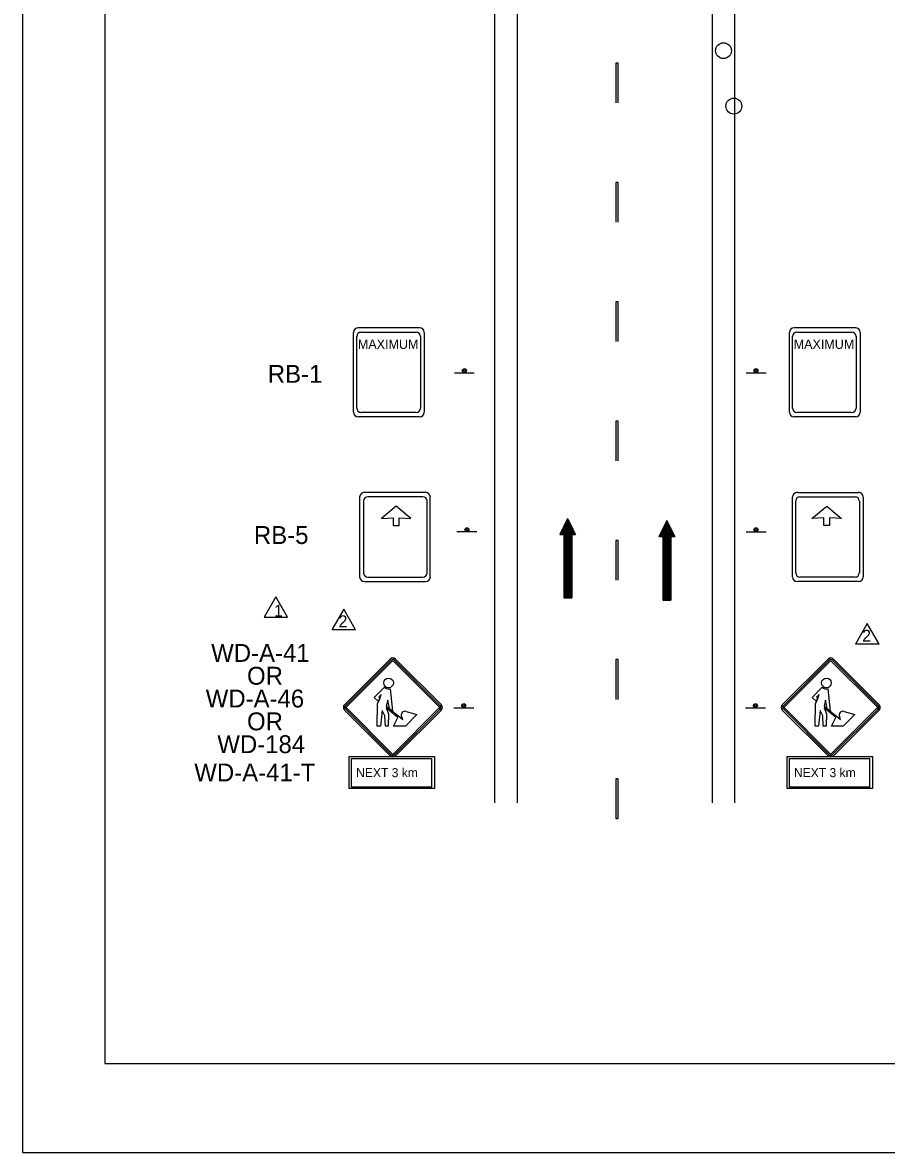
# Model space of a CAD drawing. Extents: x 1333 to 1549, y 120 to 399.
# Drawn here: x 1333.4 to 1438.4, y 119.8 to 257.2 of the extents above; entities that cross this region are included whole.
import ezdxf

# ---------------------------------------------------------------- set-up
doc = ezdxf.new("R2010")
doc.units = 0
for name, color, linetype in [('Level 1', 7, 'Continuous'), ('Level 10', 7, 'Continuous'), ('Level 2', 7, 'Continuous'), ('Level 44', 7, 'Continuous'), ('Level 5', 7, 'Continuous'), ('Level 60', 7, 'Continuous'), ('Level 63', 7, 'Continuous')]:
    doc.layers.add(name, color=color, linetype=linetype)

msp = doc.modelspace()

# ---------------------------------------------------------------- linework, layer by layer
at = {"layer": 'Level 1'}
for p, q in [((1378.07, 179.78), (1372.49, 174.21)), ((1378.19, 179.66), (1372.62, 174.09)), ((1378.32, 179.53), (1372.74, 173.96)), ((1384.03, 173.96), (1378.45, 179.53)), ((1384.15, 174.08), (1378.58, 179.66)), ((1384.28, 174.21), (1378.7, 179.78)), ((1431.32, 179.78), (1425.74, 174.21)), ((1431.44, 179.66), (1425.87, 174.09)), ((1431.57, 179.53), (1425.99, 173.96)), ((1437.28, 173.96), (1431.7, 179.53)), ((1437.4, 174.08), (1431.83, 179.66)), ((1437.52, 174.21), (1431.95, 179.78)), ((1378.13, 177.34), (1378.11, 177.34)), ((1431.37, 177.34), (1431.36, 177.34)), ((1372.49, 173.58), (1378.07, 168.01)), ((1372.62, 173.71), (1378.19, 168.13)), ((1372.74, 173.83), (1378.32, 168.25)), ((1378.45, 168.25), (1384.03, 173.83)), ((1378.57, 168.13), (1384.15, 173.7)), ((1378.7, 168.01), (1384.28, 173.58)), ((1425.74, 173.58), (1431.32, 168.01)), ((1425.87, 173.71), (1431.44, 168.13)), ((1425.99, 173.83), (1431.56, 168.25)), ((1431.7, 168.25), (1437.28, 173.83)), ((1431.82, 168.13), (1437.4, 173.7)), ((1431.95, 168.01), (1437.52, 173.58))]:
    msp.add_line(p, q, dxfattribs=at)
for points in [[(1364.16, 187.35), (1362.75, 184.88), (1365.58, 184.88)], [(1376.66, 175.13), (1376.8, 175.02), (1376.97, 175.45)], [(1377.97, 173.75), (1377.76, 174.77), (1377.59, 174.06)], [(1429.91, 175.13), (1430.05, 175.02), (1430.22, 175.45)], [(1431.21, 173.75), (1431.01, 174.77), (1430.84, 174.06)]]:
    msp.add_lwpolyline(points, close=True, dxfattribs=at)
for points in [[(1376.66, 175.13), (1376.8, 175.02), (1376.64, 174.62), (1376.13, 175.1), (1377.35, 176.35)], [(1376.66, 175.13), (1376.8, 175.02), (1376.64, 174.62), (1376.13, 175.1), (1377.35, 176.35)], [(1377.08, 173.52), (1376.9, 171.62), (1376.48, 171.62), (1376.53, 174.35), (1376.64, 174.62), (1376.13, 175.1), (1377.35, 176.35)], [(1378.05, 176.17), (1378.33, 173.45), (1377.97, 173.75), (1377.76, 174.77), (1377.59, 174.06), (1379.58, 172.42), (1379.44, 172.78)], [(1378.05, 176.17), (1378.33, 173.45), (1377.97, 173.75), (1377.76, 174.77), (1377.59, 174.06), (1379.58, 172.42), (1379.44, 172.78)], [(1378.05, 176.17), (1378.33, 173.45), (1379.58, 172.42), (1379.44, 172.78)], [(1429.91, 175.13), (1430.05, 175.02), (1429.89, 174.62), (1429.38, 175.1), (1430.6, 176.35)], [(1429.91, 175.13), (1430.05, 175.02), (1429.89, 174.62), (1429.38, 175.1), (1430.6, 176.35)], [(1430.33, 173.52), (1430.15, 171.62), (1429.72, 171.62), (1429.78, 174.35), (1429.89, 174.62), (1429.38, 175.1), (1430.6, 176.35)], [(1431.29, 176.17), (1431.58, 173.45), (1431.21, 173.75), (1431.01, 174.77), (1430.84, 174.06), (1432.83, 172.42), (1432.69, 172.78)], [(1431.29, 176.17), (1431.58, 173.45), (1431.21, 173.75), (1431.01, 174.77), (1430.84, 174.06), (1432.83, 172.42), (1432.69, 172.78)], [(1431.29, 176.17), (1431.58, 173.45), (1432.83, 172.42), (1432.69, 172.78)], [(1380.02, 173.4), (1381.3, 173.02), (1379.91, 171.62), (1378.46, 171.62), (1379, 172.68), (1377.59, 173.83), (1377.87, 173.1), (1377.83, 171.62), (1377.48, 171.62), (1377.42, 172.88), (1377.08, 173.52), (1376.9, 171.62), (1376.48, 171.62), (1376.53, 174.35), (1376.97, 175.45), (1376.66, 175.13)], [(1380.02, 173.4), (1381.3, 173.02), (1379.91, 171.62), (1378.46, 171.62), (1379, 172.68), (1377.59, 173.83), (1377.87, 173.1), (1377.83, 171.62), (1377.48, 171.62), (1377.42, 172.88), (1377.08, 173.52), (1376.9, 171.62), (1376.48, 171.62), (1376.53, 174.35), (1376.97, 175.45), (1376.66, 175.13)], [(1433.27, 173.4), (1434.55, 173.02), (1433.16, 171.62), (1431.71, 171.62), (1432.25, 172.68), (1430.84, 173.83), (1431.12, 173.1), (1431.08, 171.62), (1430.73, 171.62), (1430.67, 172.88), (1430.33, 173.52), (1430.15, 171.62), (1429.72, 171.62), (1429.78, 174.35), (1430.22, 175.45), (1429.91, 175.13)], [(1433.27, 173.4), (1434.55, 173.02), (1433.16, 171.62), (1431.71, 171.62), (1432.25, 172.68), (1430.84, 173.83), (1431.12, 173.1), (1431.08, 171.62), (1430.73, 171.62), (1430.67, 172.88), (1430.33, 173.52), (1430.15, 171.62), (1429.72, 171.62), (1429.78, 174.35), (1430.22, 175.45), (1429.91, 175.13)], [(1380.02, 173.4), (1381.3, 173.02), (1379.91, 171.62), (1378.46, 171.62), (1379, 172.68), (1377.59, 173.83), (1377.87, 173.1), (1377.83, 171.62), (1377.48, 171.62), (1377.42, 172.88), (1377.08, 173.52)], [(1433.27, 173.4), (1434.55, 173.02), (1433.16, 171.62), (1431.71, 171.62), (1432.25, 172.68), (1430.84, 173.83), (1431.12, 173.1), (1431.08, 171.62), (1430.73, 171.62), (1430.67, 172.88), (1430.33, 173.52)]]:
    msp.add_lwpolyline(points, dxfattribs=at)
for centre in [(1377.86, 176.88), (1377.86, 176.88), (1377.86, 176.88), (1431.11, 176.88), (1431.11, 176.88), (1431.11, 176.88)]:
    msp.add_circle(centre, 0.591, dxfattribs=at)
for centre, radius, start, end in [((1378.39, 179.47), 0.446, 45, 134.9651), ((1378.39, 179.47), 0.27, 45, 134.9651), ((1378.39, 179.47), 0.0948, 45, 134.9651), ((1431.63, 179.47), 0.446, 45, 134.9651), ((1431.63, 179.47), 0.27, 45, 134.9651), ((1431.63, 179.47), 0.0948, 45, 134.9651), ((1377.86, 176.88), 0.734, 226.3135, 284.9576), ((1377.86, 176.88), 0.734, 226.3135, 284.9576), ((1377.86, 176.88), 0.734, 226.3135, 284.9576), ((1431.11, 176.88), 0.734, 226.3135, 284.9576), ((1431.11, 176.88), 0.734, 226.3135, 284.9576), ((1431.11, 176.88), 0.734, 226.3135, 284.9576), ((1372.81, 173.9), 0.446, 134.965, 225), ((1372.81, 173.9), 0.27, 134.965, 225), ((1372.81, 173.9), 0.0948, 134.965, 225), ((1379.88, 172.95), 0.475, 73.381, 201.0999), ((1379.88, 172.95), 0.475, 73.381, 201.0999), ((1379.88, 172.95), 0.475, 73.381, 201.0999), ((1383.96, 173.89), 0.0948, 314.9651, 45), ((1383.96, 173.89), 0.27, 314.9651, 45), ((1383.96, 173.89), 0.446, 314.9651, 45), ((1426.06, 173.9), 0.446, 134.965, 225), ((1426.06, 173.9), 0.27, 134.965, 225), ((1426.06, 173.9), 0.0948, 134.965, 225), ((1433.13, 172.95), 0.475, 73.381, 201.0999), ((1433.13, 172.95), 0.475, 73.381, 201.0999), ((1433.13, 172.95), 0.475, 73.381, 201.0999), ((1437.21, 173.89), 0.0948, 314.9651, 45), ((1437.21, 173.89), 0.27, 314.9651, 45), ((1437.21, 173.89), 0.446, 314.9651, 45), ((1378.38, 168.32), 0.446, 225, 314.9652), ((1378.38, 168.32), 0.27, 225, 314.9652), ((1378.38, 168.32), 0.0948, 225, 314.9652), ((1431.63, 168.32), 0.446, 225, 314.9652), ((1431.63, 168.32), 0.27, 225, 314.9652), ((1431.63, 168.32), 0.0948, 225, 314.9652)]:
    msp.add_arc(centre, radius, start, end, dxfattribs=at)
at = {"layer": 'Level 10'}
for p, q in [((1390.76, 343.79), (1390.76, 162.28)), ((1393.49, 343.79), (1393.49, 162.28)), ((1417.2, 343.79), (1417.2, 162.28)), ((1419.94, 343.79), (1419.94, 162.28)), ((1417.42, 237.37), (1417.43, 237.37)), ((1399.64, 196.89), (1398.68, 194.95)), ((1399.52, 196.64), (1399.52, 187.21)), ((1399.64, 196.89), (1399.64, 187.21)), ((1399.64, 196.89), (1400.61, 194.95)), ((1399.77, 196.64), (1399.77, 187.21)), ((1411.7, 196.62), (1410.74, 194.69)), ((1411.7, 196.62), (1411.7, 186.94)), ((1411.7, 196.62), (1412.67, 194.69)), ((1398.92, 195.44), (1398.92, 194.95)), ((1399.04, 195.68), (1399.04, 194.95)), ((1399.16, 195.92), (1399.16, 187.21)), ((1399.28, 196.16), (1399.28, 187.21)), ((1399.4, 196.4), (1399.4, 187.21)), ((1399.89, 196.4), (1399.89, 187.21)), ((1400.01, 196.16), (1400.01, 187.21)), ((1400.13, 195.92), (1400.13, 187.21)), ((1400.25, 195.68), (1400.25, 194.95)), ((1400.37, 195.44), (1400.37, 194.95)), ((1411.1, 195.41), (1411.1, 194.69)), ((1411.22, 195.65), (1411.22, 186.94)), ((1411.34, 195.9), (1411.34, 186.94)), ((1411.46, 196.14), (1411.46, 186.94)), ((1411.58, 196.38), (1411.58, 186.94)), ((1411.83, 196.38), (1411.83, 186.94)), ((1411.95, 196.14), (1411.95, 186.94)), ((1412.07, 195.9), (1412.07, 186.94)), ((1412.19, 195.65), (1412.19, 186.94)), ((1412.31, 195.41), (1412.31, 194.69)), ((1398.68, 194.95), (1399.16, 194.95)), ((1398.8, 195.19), (1398.8, 194.95)), ((1399.16, 194.95), (1399.16, 187.21)), ((1400.13, 194.95), (1400.13, 187.21)), ((1400.13, 194.95), (1400.61, 194.95)), ((1400.49, 195.19), (1400.49, 194.95)), ((1410.74, 194.69), (1411.22, 194.69)), ((1410.86, 194.93), (1410.86, 194.69)), ((1410.98, 195.17), (1410.98, 194.69)), ((1411.22, 194.69), (1411.22, 186.94)), ((1412.19, 194.69), (1412.19, 186.94)), ((1412.19, 194.69), (1412.67, 194.69)), ((1412.43, 195.17), (1412.43, 194.69)), ((1412.55, 194.93), (1412.55, 194.69)), ((1399.16, 187.21), (1400.13, 187.21)), ((1411.22, 186.94), (1412.19, 186.94)), ((1390.76, 162.28), (1390.76, 162.28))]:
    msp.add_line(p, q, dxfattribs=at)
for centre in [(1418.59, 253.8), (1419.85, 247.06)]:
    msp.add_circle(centre, 0.968, dxfattribs=at)
at = {"layer": 'Level 2'}
for p, q in [((1405.51, 252.28), (1405.51, 247.44)), ((1405.8, 252.28), (1405.51, 252.28)), ((1405.8, 247.44), (1405.8, 252.28)), ((1405.51, 237.77), (1405.51, 232.93)), ((1405.8, 237.77), (1405.51, 237.77)), ((1405.8, 232.93), (1405.8, 237.77)), ((1405.51, 223.25), (1405.51, 218.41)), ((1405.8, 223.25), (1405.51, 223.25)), ((1405.8, 218.41), (1405.8, 223.25)), ((1405.51, 208.74), (1405.51, 203.9)), ((1405.8, 208.74), (1405.51, 208.74)), ((1405.8, 203.9), (1405.8, 208.74)), ((1405.51, 194.22), (1405.51, 189.39)), ((1405.8, 194.22), (1405.51, 194.22)), ((1405.8, 189.39), (1405.8, 194.22)), ((1405.51, 179.71), (1405.51, 174.87)), ((1405.8, 179.71), (1405.51, 179.71)), ((1405.8, 174.87), (1405.8, 179.71)), ((1405.51, 165.2), (1405.51, 160.36)), ((1405.8, 165.2), (1405.51, 165.2)), ((1405.8, 160.36), (1405.8, 165.2)), ((1405.51, 160.36), (1405.8, 160.36))]:
    msp.add_line(p, q, dxfattribs=at)
at = {"layer": 'Level 44'}
for p, q in [((1374.18, 220.1), (1381.63, 220.1)), ((1427.18, 220.1), (1434.63, 220.1)), ((1373.61, 209.82), (1373.61, 219.53)), ((1373.99, 210.31), (1373.99, 219.05)), ((1374.51, 219.56), (1381.21, 219.56)), ((1381.73, 219.05), (1381.73, 210.31)), ((1382.2, 219.53), (1382.2, 209.82)), ((1426.6, 209.82), (1426.6, 219.53)), ((1426.99, 210.31), (1426.99, 219.05)), ((1427.5, 219.56), (1434.21, 219.56)), ((1434.73, 219.05), (1434.73, 210.31)), ((1435.2, 219.53), (1435.2, 209.82)), ((1385.88, 214.59), (1388.29, 214.59)), ((1421.34, 214.59), (1423.76, 214.59)), ((1373.61, 209.81), (1373.61, 209.82)), ((1373.99, 210.31), (1373.99, 210.31)), ((1381.63, 209.24), (1374.18, 209.24)), ((1374.31, 209.48), (1374.31, 209.48)), ((1381.21, 209.79), (1374.51, 209.79)), ((1426.6, 209.81), (1426.6, 209.82)), ((1426.99, 210.31), (1426.99, 210.31)), ((1434.63, 209.24), (1427.18, 209.24)), ((1434.21, 209.79), (1427.5, 209.79)), ((1374.34, 199.49), (1374.34, 189.78)), ((1382.37, 200.06), (1374.92, 200.06)), ((1382.04, 199.53), (1375.34, 199.53)), ((1382.94, 189.78), (1382.94, 199.49)), ((1426.99, 189.78), (1426.99, 199.49)), ((1427.57, 200.06), (1435.01, 200.06)), ((1427.89, 199.53), (1434.6, 199.53)), ((1435.59, 199.49), (1435.59, 189.78)), ((1374.82, 199.01), (1374.82, 190.27)), ((1382.56, 190.27), (1382.56, 199.01)), ((1427.38, 190.27), (1427.38, 199.01)), ((1435.11, 199.01), (1435.11, 190.27)), ((1388.59, 195.24), (1386.17, 195.24)), ((1421.34, 195.24), (1423.76, 195.24)), ((1375.34, 189.75), (1382.04, 189.75)), ((1382.56, 190.27), (1382.56, 190.27)), ((1382.94, 189.78), (1382.94, 189.78)), ((1426.99, 189.78), (1426.99, 189.78)), ((1427.38, 190.27), (1427.38, 190.27)), ((1434.6, 189.75), (1427.89, 189.75)), ((1374.92, 189.2), (1382.37, 189.2)), ((1435.01, 189.2), (1427.57, 189.2)), ((1385.8, 173.85), (1388.22, 173.85)), ((1421.27, 173.85), (1423.69, 173.85))]:
    msp.add_line(p, q, dxfattribs=at)
for points in [[(1380.59, 196.89), (1378.79, 198.4), (1376.99, 196.89), (1378.43, 196.97), (1378.43, 196.01), (1379.15, 196.01), (1379.15, 196.97)], [(1429.34, 196.89), (1431.14, 198.4), (1432.94, 196.89), (1431.5, 196.97), (1431.5, 196.01), (1430.78, 196.01), (1430.78, 196.97)]]:
    msp.add_lwpolyline(points, close=True, dxfattribs=at)
for centre, radius in [((1387.09, 214.87), 0.242), ((1387.09, 214.87), 0.121), ((1422.55, 214.87), 0.242), ((1422.55, 214.87), 0.121), ((1387.38, 195.51), 0.242), ((1387.38, 195.51), 0.121), ((1422.55, 195.51), 0.242), ((1422.55, 195.51), 0.121), ((1387.01, 174.12), 0.242), ((1387.01, 174.12), 0.121), ((1422.48, 174.12), 0.242), ((1422.48, 174.12), 0.121)]:
    msp.add_circle(centre, radius, dxfattribs=at)
for centre, radius, start, end in [((1374.18, 219.52), 0.575, 90, 180), ((1381.63, 219.52), 0.575, 360, 90), ((1427.18, 219.52), 0.575, 90, 180), ((1434.63, 219.52), 0.575, 360, 90), ((1374.51, 219.04), 0.517, 90, 180), ((1381.21, 219.04), 0.517, 360, 90), ((1427.5, 219.04), 0.517, 90, 180), ((1434.21, 219.04), 0.517, 360, 90), ((1374.18, 209.81), 0.575, 180, 270), ((1374.51, 210.31), 0.517, 180, 270), ((1381.21, 210.31), 0.517, 270, 360), ((1381.63, 209.81), 0.575, 270, 360), ((1427.18, 209.81), 0.575, 180, 270), ((1427.5, 210.31), 0.517, 180, 270), ((1434.21, 210.31), 0.517, 270, 360), ((1434.63, 209.81), 0.575, 270, 360), ((1374.92, 199.49), 0.575, 90, 180), ((1375.34, 199.01), 0.517, 90, 180), ((1382.04, 199.01), 0.517, 0, 90), ((1382.37, 199.49), 0.575, 0, 90), ((1427.57, 199.49), 0.575, 90, 180), ((1427.89, 199.01), 0.517, 90, 180), ((1434.59, 199.01), 0.517, 360, 90), ((1435.01, 199.49), 0.575, 360, 90), ((1374.92, 189.78), 0.575, 180, 270), ((1375.34, 190.27), 0.517, 180, 270), ((1382.04, 190.27), 0.517, 270, 0), ((1382.37, 189.78), 0.575, 270, 0), ((1427.57, 189.78), 0.575, 180, 270), ((1427.89, 190.27), 0.517, 180, 270), ((1434.59, 190.27), 0.517, 270, 360), ((1435.01, 189.78), 0.575, 270, 360)]:
    msp.add_arc(centre, radius, start, end, dxfattribs=at)
at = {"layer": 'Level 5'}
for points in [[(1373.09, 167.91), (1383.45, 167.91), (1383.45, 164.04), (1373.09, 164.04)], [(1426.34, 167.91), (1436.7, 167.91), (1436.7, 164.04), (1426.34, 164.04)], [(1373.36, 167.7), (1383.1, 167.7), (1383.1, 164.21), (1373.36, 164.21)], [(1426.61, 167.7), (1436.35, 167.7), (1436.35, 164.21), (1426.61, 164.21)]]:
    msp.add_lwpolyline(points, close=True, dxfattribs=at)
at = {"layer": 'Level 60'}
for p, q in [((1343.36, 130.56), (1343.36, 130.56)), ((1333.36, 119.75), (1333.36, 119.75))]:
    msp.add_line(p, q, dxfattribs=at)
for points in [[(1549.36, 398.75), (1333.36, 398.75), (1333.36, 119.75), (1549.36, 119.75)], [(1530.24, 387.94), (1343.36, 387.94), (1343.36, 130.56), (1530.24, 130.56)]]:
    msp.add_lwpolyline(points, close=True, dxfattribs=at)
at = {"layer": 'Level 63'}
for points in [[(1372.41, 185.86), (1371.01, 183.43)], [(1373.8, 183.43), (1372.41, 185.86)], [(1371.01, 183.43), (1370.99, 183.39), (1373.83, 183.39), (1373.8, 183.43)], [(1436.08, 184.09), (1434.68, 181.67)], [(1437.47, 181.67), (1436.08, 184.09)], [(1434.68, 181.67), (1434.66, 181.62), (1437.5, 181.62), (1437.47, 181.67)]]:
    msp.add_lwpolyline(points, dxfattribs=at)

# ---------------------------------------------------------------- texts
at = {"layer": 'Level 1'}
msp.add_text('1', height=1.45, rotation=360, dxfattribs=at).set_placement((1363.94, 184.94))
at = {"layer": 'Level 10'}
for s, rotation, p in [('RB-1', 360, (1363.18, 213.39)), ('RB-5', 0, (1361.49, 193.78)), ('WD-A-41', 360, (1356.29, 179.44)), ('OR', 360, (1360.65, 176.66)), ('WD-A-46', 360, (1355.63, 173.89)), ('OR', 360, (1360.65, 171.11)), ('WD-184', 360, (1357.04, 168.33)), ('WD-A-41-T', 360, (1354.24, 164.89))]:
    msp.add_text(s, height=2.177, rotation=rotation, dxfattribs=at).set_placement(p)
at = {"layer": 'Level 44'}
for s, height, p in [('MAXIMUM', 1.139, (1374.13, 217.52)), ('MAXIMUM', 1.139, (1427.13, 217.52)), ('2', 1.45, (1371.78, 183.65)), ('2', 1.45, (1435.45, 181.89))]:
    msp.add_text(s, height=height, rotation=360, dxfattribs=at).set_placement(p)
at = {"layer": 'Level 5'}
for p in [(1373.92, 165.41), (1427.16, 165.41)]:
    msp.add_text('NEXT 3 km', height=1.098, rotation=360, dxfattribs=at).set_placement(p)

doc.saveas('drawing.dxf')
